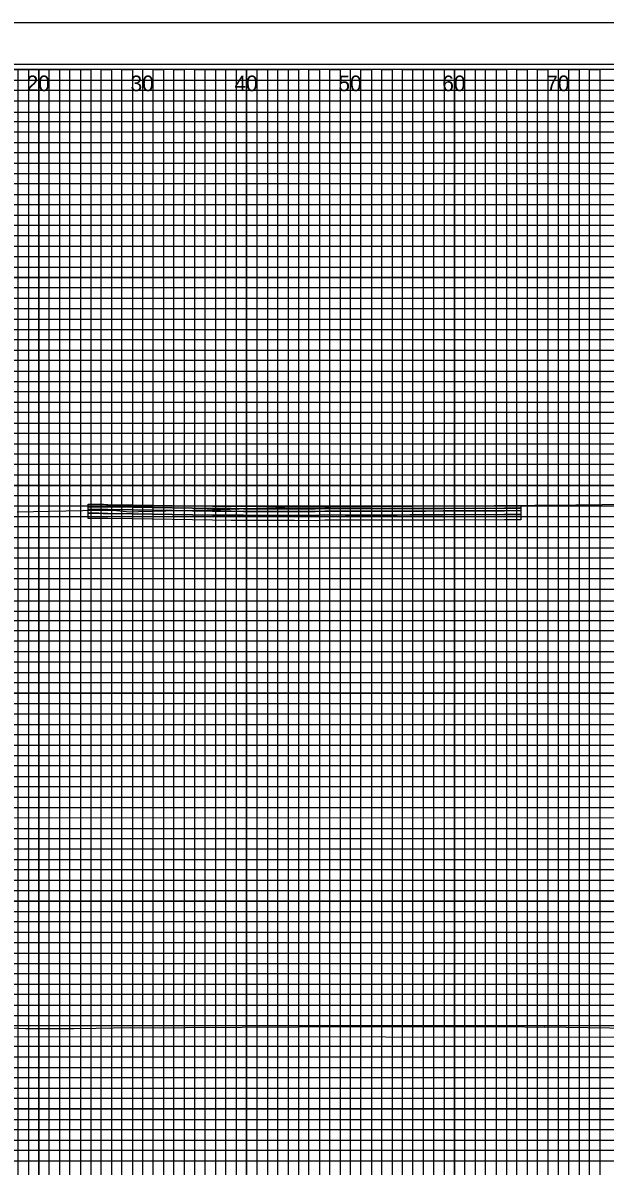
# Model space of a CAD drawing. Extents: x -13 to 760, y -5 to 1491.
# Drawn here: x 178.5 to 234.5, y 742.5 to 852.5 of the extents above; entities that cross this region are included whole.
import ezdxf

# ---------------------------------------------------------------- set-up
doc = ezdxf.new("R2010")
doc.units = 0
for name, color, linetype in [('Exist XS Ground Line', 7, 'Continuous'), ('Prop CMT Pvmt Course 1', 7, 'Continuous'), ('Prop CMT Pvmt Course 2', 7, 'Continuous'), ('Prop CMT Pvmt Course 3', 7, 'Continuous'), ('Prop CMT Pvmt Course 4', 7, 'Continuous'), ('Prop XS Offset Labels', 7, 'Continuous'), ('Scratch_Level_6', 7, 'Continuous'), ('Sheet Cross Section CELL', 7, 'Continuous'), ('Sheet Cross Section Grid Major CELL', 7, 'Continuous'), ('Sheet Cross Section Grid Middle CELL', 7, 'Continuous'), ('Sheet Cross Section Grid Minor 1 CELL', 7, 'Continuous'), ('Sheet Cross Section Grid Minor 2 CELL', 7, 'Continuous'), ('Sheet Cutting Line CELL', 7, 'Continuous'), ('Sheet DOT Grid CELL', 7, 'Continuous'), ('Sheet Plot Border Inside CELL', 7, 'Continuous'), ('Sheet Plot Border Outside CELL', 7, 'Continuous')]:
    doc.layers.add(name, color=color, linetype=linetype)

msp = doc.modelspace()

# ---------------------------------------------------------------- linework, layer by layer
at = {"layer": 'Exist XS Ground Line'}
for points in [[(177.91, 805.47), (182.59, 805.56), (185.86, 805.64), (187.49, 805.59), (188.77, 805.46), (189.59, 805.48), (197.52, 805.7), (204.57, 805.94), (206.67, 805.96), (206.86, 805.96), (208.08, 805.96), (231.68, 806.15), (249.37, 806.35)], [(177.91, 805.47), (182.59, 805.56), (185.86, 805.64), (187.49, 805.59), (188.77, 805.46), (189.59, 805.48), (197.52, 805.7), (204.57, 805.94), (206.67, 805.96), (206.86, 805.96), (208.08, 805.96), (231.68, 806.15), (249.37, 806.35)], [(176.68, 755.86), (178.75, 755.74), (180.77, 755.74), (183.37, 755.76), (185.52, 755.78), (188.83, 755.84), (190.59, 755.83), (194.11, 755.84), (205.01, 755.9), (224.88, 755.95), (228.64, 755.87), (228.68, 755.91), (237.03, 755.8)], [(176.68, 755.86), (178.75, 755.74), (180.77, 755.74), (183.37, 755.76), (185.52, 755.78), (188.83, 755.84), (190.59, 755.83), (194.11, 755.84), (205.01, 755.9), (224.88, 755.95), (228.64, 755.87), (228.68, 755.91), (237.03, 755.8)]]:
    msp.add_lwpolyline(points, dxfattribs=at)
at = {"layer": 'Prop CMT Pvmt Course 1'}
msp.add_lwpolyline([(188.98, 806.15), (196.72, 806.02), (198.51, 806.02), (199.71, 806), (201.53, 806), (202.28, 806), (204.19, 805.99), (204.59, 805.99), (204.6, 805.99), (206.6, 805.99), (207.53, 806.03), (209.51, 806.02), (210.62, 806.03), (212.59, 806.03), (214.5, 806.03), (215.73, 806.03), (217.21, 806.04), (218.91, 806.05), (224.81, 806.07), (226.39, 806.08), (226.39, 805.83), (224.81, 805.82), (218.91, 805.8), (217.21, 805.79), (215.73, 805.78), (214.5, 805.78), (212.59, 805.78), (210.62, 805.78), (209.51, 805.77), (207.53, 805.78), (206.6, 805.74), (204.6, 805.74), (204.59, 805.74), (204.19, 805.74), (202.28, 805.75), (201.53, 805.75), (199.71, 805.75), (198.51, 805.77), (196.72, 805.77), (188.98, 805.9), (186.63, 805.93), (186.52, 805.93), (186.5, 805.93), (186.23, 805.94), (186.19, 805.94), (185.77, 805.94), (185.62, 805.94), (185.15, 805.95), (185.02, 805.95), (184.75, 805.95), (184.75, 805.95), (184.75, 806.2), (184.75, 806.2), (185.02, 806.2), (185.15, 806.2), (185.62, 806.19), (185.77, 806.19), (186.19, 806.19), (186.23, 806.19), (186.5, 806.18), (186.52, 806.18), (186.63, 806.18), (188.98, 806.15)], dxfattribs=at)
at = {"layer": 'Prop CMT Pvmt Course 2'}
msp.add_lwpolyline([(188.98, 805.9), (196.72, 805.77), (198.51, 805.77), (199.71, 805.75), (201.53, 805.75), (202.28, 805.75), (204.19, 805.74), (204.59, 805.74), (204.6, 805.74), (206.6, 805.74), (207.53, 805.78), (209.51, 805.77), (210.62, 805.78), (212.59, 805.78), (214.5, 805.78), (215.73, 805.78), (217.21, 805.79), (218.91, 805.8), (224.81, 805.82), (226.39, 805.83), (226.39, 805.58), (224.81, 805.57), (218.91, 805.55), (217.21, 805.54), (215.73, 805.53), (214.5, 805.53), (212.59, 805.53), (210.62, 805.53), (209.51, 805.52), (207.53, 805.53), (206.6, 805.49), (204.6, 805.49), (204.59, 805.49), (204.19, 805.49), (202.28, 805.5), (201.53, 805.5), (199.71, 805.5), (198.51, 805.52), (196.72, 805.52), (188.98, 805.65), (186.63, 805.68), (186.52, 805.68), (186.5, 805.68), (186.23, 805.69), (186.19, 805.69), (185.77, 805.69), (185.62, 805.69), (185.15, 805.7), (185.02, 805.7), (184.75, 805.7), (184.75, 805.7), (184.75, 805.95), (184.75, 805.95), (185.02, 805.95), (185.15, 805.95), (185.62, 805.94), (185.77, 805.94), (186.19, 805.94), (186.23, 805.94), (186.5, 805.93), (186.52, 805.93), (186.63, 805.93), (188.98, 805.9)], dxfattribs=at)
at = {"layer": 'Prop CMT Pvmt Course 3'}
msp.add_lwpolyline([(188.98, 805.65), (196.72, 805.52), (198.51, 805.52), (199.71, 805.5), (201.53, 805.5), (202.28, 805.5), (204.19, 805.49), (204.59, 805.49), (204.6, 805.49), (206.6, 805.49), (207.53, 805.53), (209.51, 805.52), (210.62, 805.53), (212.59, 805.53), (214.5, 805.53), (215.73, 805.53), (217.21, 805.54), (218.91, 805.55), (224.81, 805.57), (226.39, 805.58), (226.39, 805.21), (224.81, 805.2), (218.91, 805.17), (217.21, 805.17), (215.73, 805.16), (214.5, 805.15), (212.59, 805.15), (210.62, 805.15), (209.51, 805.15), (207.53, 805.16), (206.6, 805.11), (204.6, 805.12), (204.59, 805.12), (204.19, 805.12), (202.28, 805.12), (201.53, 805.12), (199.71, 805.13), (198.51, 805.14), (196.72, 805.15), (188.98, 805.28), (186.63, 805.31), (186.52, 805.31), (186.5, 805.31), (186.23, 805.31), (186.19, 805.31), (185.77, 805.32), (185.62, 805.32), (185.15, 805.32), (185.02, 805.33), (184.75, 805.33), (184.75, 805.33), (184.75, 805.7), (184.75, 805.7), (185.02, 805.7), (185.15, 805.7), (185.62, 805.69), (185.77, 805.69), (186.19, 805.69), (186.23, 805.69), (186.5, 805.68), (186.52, 805.68), (186.63, 805.68), (188.98, 805.65)], dxfattribs=at)
at = {"layer": 'Prop CMT Pvmt Course 4'}
msp.add_lwpolyline([(188.98, 805.28), (196.72, 805.15), (198.51, 805.14), (199.71, 805.13), (201.53, 805.12), (202.28, 805.12), (204.19, 805.12), (204.59, 805.12), (204.6, 805.12), (206.6, 805.11), (207.53, 805.16), (209.51, 805.15), (210.62, 805.15), (212.59, 805.15), (214.5, 805.15), (215.73, 805.16), (217.21, 805.17), (218.91, 805.17), (224.81, 805.2), (226.39, 805.21), (226.39, 804.71), (224.81, 804.7), (218.91, 804.67), (217.21, 804.67), (215.73, 804.66), (214.5, 804.65), (212.59, 804.65), (210.62, 804.65), (209.51, 804.65), (207.53, 804.66), (206.6, 804.61), (204.6, 804.62), (204.59, 804.62), (204.19, 804.62), (202.28, 804.62), (201.53, 804.62), (199.71, 804.63), (198.51, 804.64), (196.72, 804.65), (188.98, 804.78), (186.63, 804.81), (186.52, 804.81), (186.5, 804.81), (186.23, 804.81), (186.19, 804.81), (185.77, 804.82), (185.62, 804.82), (185.15, 804.82), (185.02, 804.83), (184.75, 804.83), (184.75, 804.83), (184.75, 805.33), (184.75, 805.33), (185.02, 805.33), (185.15, 805.32), (185.62, 805.32), (185.77, 805.32), (186.19, 805.31), (186.23, 805.31), (186.5, 805.31), (186.52, 805.31), (186.63, 805.31), (188.98, 805.28)], dxfattribs=at)
at = {"layer": 'Scratch_Level_6'}
msp.add_lwpolyline([(184.75, 806.2), (184.75, 806.2), (185.02, 806.2), (185.15, 806.2), (185.62, 806.19), (185.77, 806.19), (186.19, 806.19), (186.23, 806.19), (186.5, 806.18), (186.52, 806.18), (186.63, 806.18), (188.98, 806.15), (196.72, 806.02), (198.51, 806.02), (199.71, 806), (201.53, 806), (202.28, 806), (204.19, 805.99), (204.59, 805.99), (204.6, 805.99), (206.6, 805.99), (207.53, 806.03), (209.51, 806.02), (210.62, 806.03), (212.59, 806.03), (214.5, 806.03), (215.73, 806.03), (217.21, 806.04), (218.91, 806.05), (224.81, 806.07), (226.39, 806.08)], dxfattribs=at)
at = {"layer": 'Sheet Cross Section CELL'}
msp.add_lwpolyline([(320, 848.01), (0, 848.01), (0, 638.01), (320, 638.01)], close=True, dxfattribs=at)
at = {"layer": 'Sheet Cross Section Grid Major CELL'}
for p, q in [((190, 848.01), (180, 848.01)), ((180, 848.01), (180, 638.01)), ((190, 638.01), (190, 848.01)), ((210, 848.01), (200, 848.01)), ((200, 848.01), (200, 638.01)), ((210, 638.01), (210, 848.01)), ((230, 848.01), (220, 848.01)), ((220, 848.01), (220, 638.01)), ((230, 638.01), (230, 848.01))]:
    msp.add_line(p, q, dxfattribs=at)
for points in [[(0, 838.01), (320, 838.01), (320, 828.01), (0, 828.01)], [(0, 818.01), (320, 818.01), (320, 808.01), (0, 808.01)], [(0, 798.01), (320, 798.01), (320, 788.01), (0, 788.01)], [(0, 778.01), (320, 778.01), (320, 768.01), (0, 768.01)], [(0, 758.01), (320, 758.01), (320, 748.01), (0, 748.01)]]:
    msp.add_lwpolyline(points, dxfattribs=at)
at = {"layer": 'Sheet Cross Section Grid Middle CELL'}
for points in [[(175, 638.01), (175, 848.01), (185, 848.01), (185, 638.01)], [(195, 638.01), (195, 848.01), (205, 848.01), (205, 638.01)], [(215, 638.01), (215, 848.01), (225, 848.01), (225, 638.01)], [(0, 843.01), (275, 843.01)], [(0, 823.01), (320, 823.01), (320, 833.01), (0, 833.01)], [(0, 803.01), (320, 803.01), (320, 813.01), (0, 813.01)], [(0, 783.01), (320, 783.01), (320, 793.01), (0, 793.01)], [(0, 763.01), (320, 763.01), (320, 773.01), (0, 773.01)], [(0, 743.01), (320, 743.01), (320, 753.01), (0, 753.01)]]:
    msp.add_lwpolyline(points, dxfattribs=at)
at = {"layer": 'Sheet Cross Section Grid Minor 1 CELL'}
for p, q in [((0, 847.01), (260, 847.01)), ((260, 845.99), (0, 845.99)), ((0, 845.01), (260, 845.01)), ((260, 843.9), (0, 843.9)), ((0, 842.01), (320, 842.01))]:
    msp.add_line(p, q, dxfattribs=at)
for points in [[(0, 841.01), (270, 841.01), (320, 841.01), (320, 840.01), (0, 840.01)], [(0, 839.01), (320, 839.01), (320, 837.01), (0, 837.01)], [(0, 836.01), (320, 836.01), (320, 835.01), (0, 834.99)], [(0, 834.01), (320, 834.01), (320, 832.01), (0, 832.01)], [(0, 831.01), (320, 831.01), (320, 830.01), (0, 830.01)], [(0, 829.01), (320, 829.01), (320, 827.01), (0, 827.01)], [(0, 826.01), (320, 826.01), (320, 825.01), (0, 825.01)], [(0, 824.01), (320, 824.01), (320, 822.01), (0, 822.01)], [(0, 821.01), (320, 821.01), (320, 820.01), (0, 820.01)], [(0, 819.01), (320, 819.01), (320, 817.01), (0, 817.01)], [(0, 816.01), (320, 816.01), (320, 815.01), (0, 815.01)], [(0, 814.01), (320, 814.01), (320, 811.96), (320, 811.01), (320, 810.01), (0, 810.01)], [(0, 812.01), (320, 812.01), (320, 811.01), (0, 811.01)], [(0, 809.01), (320, 809.01), (320, 807.01), (0, 807.04)], [(0, 807.04), (320, 807.01), (320, 806.01), (0, 806.01)], [(0, 805.01), (320, 805.01), (320, 804.01), (0, 804.01)], [(0, 802.01), (320, 802.01), (320, 801.01), (0, 801.01)], [(0, 800.01), (320, 800.01), (320, 799.01), (0, 799.01)], [(-0.07, 796.9), (320, 796.9), (320, 795.89), (-0.07, 795.89)], [(0, 795.01), (320, 795.01), (320, 794.01), (0, 794.01)], [(0, 792.01), (320, 792.01), (320, 791.01), (0, 791.01)], [(0, 790.01), (320, 790.01), (320, 789.01), (0, 789.01)], [(0, 787.01), (320, 787.01), (320, 786.01), (0, 786.01)], [(0, 785.01), (320, 785.01), (320, 784.01), (0, 784.01)], [(0, 782.01), (320, 782.01), (320, 781.01), (0, 781.01)], [(0, 780.01), (320, 780.01), (320, 779.01), (0, 779.01)], [(0, 777.01), (320, 777.01), (319.99, 775.99), (0, 776.01)], [(0, 775.01), (320, 775.01), (320, 774.01), (0, 774.01)], [(0, 772.01), (320, 772.01), (320, 771.01), (0, 771.01)], [(0, 770.01), (320, 770.01), (320, 769.01), (0, 769.01)], [(0, 767.01), (320, 767.01), (320, 766.01), (0, 766.01)], [(0, 765.01), (320, 765.01), (320, 764.01), (0, 764.01)], [(0, 762.01), (320, 762.01), (320, 761.01), (0, 761.01)], [(0, 760.01), (320, 760.01), (320, 759.01), (0, 759.01)], [(0, 757.01), (320, 757.01), (320, 756.01), (0, 756.01)], [(0, 755), (320.07, 754.92), (320, 754.01), (0, 754.01)], [(0, 752.01), (320, 752.01), (320, 751.01), (0, 751.01)], [(0, 750.01), (320, 750.01), (320, 749.01), (0, 749.01)], [(0, 747.01), (320, 747.01), (320, 746.01), (0, 746.01)], [(0, 745.01), (320, 745.01), (320, 744.01), (0, 744.01)]]:
    msp.add_lwpolyline(points, dxfattribs=at)
at = {"layer": 'Sheet Cross Section Grid Minor 2 CELL'}
for points in [[(177, 638.01), (178, 638.01), (178, 848.01), (179, 848.01), (179, 638.01)], [(180, 638.01), (181, 638.01), (181, 848.01), (182, 848.01), (182, 638.01)], [(182, 638.01), (183, 638.01), (183, 848.01), (184, 848.01), (184, 638.01)], [(185, 638.01), (186, 638.01), (186, 848.01), (187, 848.01), (187, 638.01)], [(187, 638.01), (188, 638.01), (188, 848.01), (189, 848.01), (189, 638.01)], [(190, 638.01), (191, 638.01), (191, 848.01), (192, 848.01), (192, 638.01)], [(192, 638.01), (193, 638.01), (193, 848.01), (194, 848.01), (194, 638.01)], [(195, 638.01), (196, 638.01), (196, 848.01), (197, 848.01), (197, 638.01)], [(197, 638.01), (198, 638.01), (198, 848.01), (199, 848.01), (199, 638.01)], [(200, 638.01), (201, 638.01), (201, 848.01), (202, 848.01), (202, 638.01)], [(202, 638.01), (203, 638.01), (203, 848.01), (204, 848.01), (204, 638.01)], [(205, 638.01), (206, 638.01), (206, 848.01), (207, 848.01), (207, 638.01)], [(207, 638.01), (208, 638.01), (208, 848.01), (209, 848.01), (209, 638.01)], [(210, 638.01), (211, 638.01), (211, 848.01), (212, 848.01), (212, 638.01)], [(212, 638.01), (213, 638.01), (213, 848.01), (214, 848.01), (214, 638.01)], [(215, 638.01), (216, 638.01), (216, 848.01), (217, 848.01), (217, 638.01)], [(217, 638.01), (218, 638.01), (218, 848.01), (219, 848.01), (219, 638.01)], [(220, 638.01), (221, 638.01), (221, 848.01), (222, 848.01), (222, 638.01)], [(222, 638.01), (223, 638.01), (223, 848.01), (224, 848.01), (224, 638.01)], [(225, 638.01), (226, 638.01), (226, 848.01), (227, 848.01), (227, 638.01)], [(227, 638.01), (228, 638.01), (228, 848.01), (229, 848.01), (229, 638.01)], [(230, 638.01), (231, 638.01), (231, 848.01), (232, 848.01), (232, 638.01)], [(232, 638.01), (233, 638.01), (233, 848.01), (234, 848.01), (234, 638.01)]]:
    msp.add_lwpolyline(points, dxfattribs=at)
at = {"layer": 'Sheet Cutting Line CELL'}
msp.add_line((323.3, 852.51), (-13.4, 852.51), dxfattribs=at)
at = {"layer": 'Sheet DOT Grid CELL'}
for p, q in [((180, 638.01), (180, 848.01)), ((190, 638.01), (190, 848.01)), ((200, 638.01), (200, 848.01)), ((210, 638.01), (210, 848.01)), ((220, 638.01), (220, 848.01)), ((230, 638.01), (230, 848.01)), ((0, 838.01), (320, 838.01)), ((0, 828.01), (320, 828.01)), ((0, 818.01), (320, 818.01)), ((0, 808.01), (320, 808.01)), ((0, 798.01), (320, 798.01)), ((0, 788.01), (320, 788.01)), ((0, 778.01), (320, 778.01)), ((0, 768.01), (320, 768.01)), ((0, 758.01), (320, 758.01)), ((0, 748.01), (320, 748.01))]:
    msp.add_line(p, q, dxfattribs=at)
at = {"layer": 'Sheet Plot Border Inside CELL'}
msp.add_lwpolyline([(-10.8, 637.51), (322.4, 637.51), (322.4, 848.51), (-10.8, 848.51)], close=True, dxfattribs=at)
at = {"layer": 'Sheet Plot Border Outside CELL'}
msp.add_lwpolyline([(-13.4, 633.51), (323.3, 633.51), (323.3, 852.51), (-13.4, 852.51)], close=True, dxfattribs=at)

# ---------------------------------------------------------------- texts
at = {"layer": 'Prop XS Offset Labels'}
for s, p in [('20', (178.83, 845.94)), ('30', (188.83, 845.94)), ('40', (198.83, 845.94)), ('50', (208.83, 845.94)), ('60', (218.83, 845.94)), ('70', (228.83, 845.94))]:
    msp.add_text(s, height=1.5, dxfattribs=at).set_placement(p)

doc.saveas('drawing.dxf')
